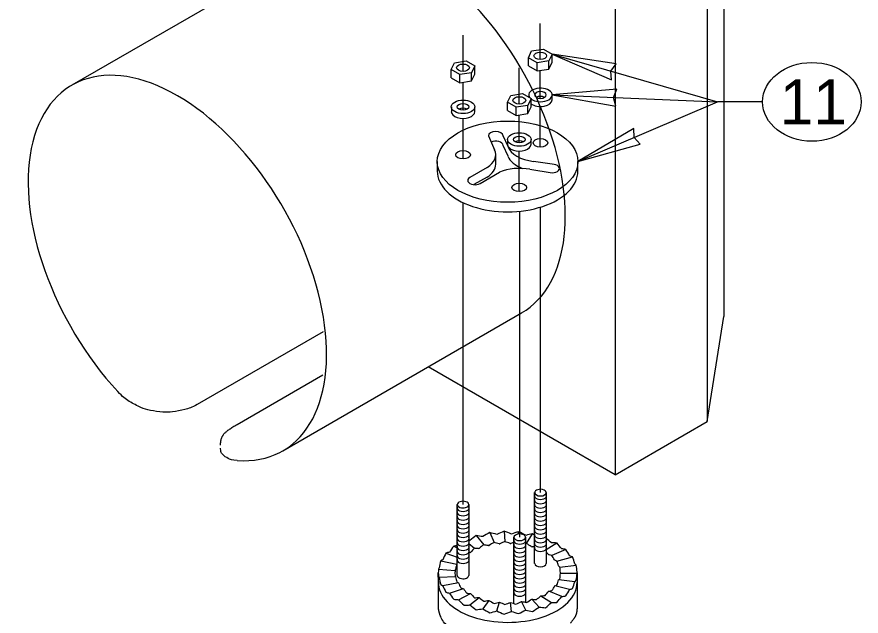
# Model space of a CAD drawing. Extents: x 99862 to 104211, y 98939 to 105076.
# Drawn here: x 100228.4 to 100528.4, y 103913.4 to 104126.3 of the extents above; entities that cross this region are included whole.
import ezdxf

# ---------------------------------------------------------------- set-up
doc = ezdxf.new("R2010")
doc.units = 0
for name, color, linetype in [('Default', 7, 'Continuous'), ('Level 1', 7, 'Continuous'), ('Level 11', 7, 'Continuous'), ('Level 13', 7, 'Continuous'), ('Level 15', 7, 'Continuous'), ('Level 20', 7, 'Continuous'), ('Level 26', 7, 'Continuous')]:
    doc.layers.add(name, color=color, linetype=linetype)

msp = doc.modelspace()

# ---------------------------------------------------------------- linework, layer by layer
at = {"layer": 'Default'}
for p, q in [((100412.41, 103932.12), (100412.41, 103957.28)), ((100412.41, 103932.12), (100412.41, 103957.28)), ((100416.52, 103957.28), (100416.52, 103932.12)), ((100416.52, 103957.28), (100416.52, 103932.12)), ((100384.91, 103927.86), (100384.91, 103953.03)), ((100384.91, 103927.86), (100384.91, 103953.03)), ((100389.02, 103953.03), (100389.02, 103927.86)), ((100389.02, 103953.03), (100389.02, 103927.86)), ((100405.04, 103917.87), (100405.04, 103941.41)), ((100405.04, 103917.87), (100405.04, 103941.41)), ((100409.15, 103941.41), (100409.15, 103918.31)), ((100409.15, 103941.41), (100409.15, 103918.31)), ((100378.18, 103917.02), (100378.18, 103925.41)), ((100427.5, 103925.41), (100427.5, 103917.02))]:
    msp.add_line(p, q, dxfattribs=at)
for centre, start_param, end_param in [((100414.47, 103957.28), 2.356194, 3.141593), ((100414.47, 103957.28), 2.356194, 3.141593), ((100414.47, 103957.28), 3.141593, 6.283185), ((100414.47, 103957.28), 3.141593, 6.283185), ((100414.47, 103957.28), 0, 2.356194), ((100414.47, 103957.28), 0, 2.356194), ((100386.96, 103953.03), 0, 3.141593), ((100386.96, 103953.03), 0, 3.141593), ((100386.96, 103953.03), 3.141593, 4.45059), ((100386.96, 103953.03), 3.141593, 4.45059), ((100386.96, 103953.03), 4.45059, 6.283185), ((100386.96, 103953.03), 4.45059, 6.283185), ((100407.1, 103941.41), 0.261799, 3.141593), ((100407.1, 103941.41), 0.261799, 3.141593), ((100407.1, 103941.41), 3.141593, 6.283185), ((100407.1, 103941.41), 3.141593, 6.283185), ((100407.1, 103941.41), 0, 0.261799), ((100407.1, 103941.41), 0, 0.261799), ((100414.47, 103932.12), 3.141593, 6.283185), ((100414.47, 103932.12), 3.141593, 6.283185), ((100386.96, 103927.86), 3.141593, 4.45059), ((100386.96, 103927.86), 3.141593, 4.45059), ((100386.96, 103927.86), 4.45059, 6.283185), ((100386.96, 103927.86), 4.45059, 6.283185)]:
    msp.add_ellipse(centre, major_axis=(2.05, 0), ratio=0.57735, start_param=start_param, end_param=end_param, dxfattribs=at)
for points, degree in [([(100413.47, 103904.17), (100412.83, 103903.99), (100412.18, 103903.83), (100411.51, 103903.69), (100408.71, 103903.08), (100405.7, 103902.77), (100402.7, 103902.78), (100397.64, 103902.79), (100392.6, 103903.74), (100388.49, 103905.44), (100386.24, 103906.37), (100384.26, 103907.52), (100382.67, 103908.83), (100380.71, 103910.44), (100379.32, 103912.29), (100378.66, 103914.23), (100378.62, 103914.36), (100378.58, 103914.48), (100378.54, 103914.61), (100378.5, 103914.74), (100378.46, 103914.88), (100378.43, 103915.01), (100378.4, 103915.15), (100378.37, 103915.28), (100378.34, 103915.42), (100378.31, 103915.55), (100378.29, 103915.69), (100378.27, 103915.83), (100378.25, 103915.96), (100378.23, 103916.1), (100378.22, 103916.23), (100378.21, 103916.37), (100378.2, 103916.51), (100378.19, 103916.64), (100378.19, 103916.77), (100378.18, 103916.89), (100378.18, 103917.02)], 3), ([(100427.5, 103917.02), (100427.5, 103914.9), (100426.67, 103912.79), (100425.09, 103910.88)], 2)]:
    msp.add_open_spline(points, degree=degree, dxfattribs=at)
at = {"layer": 'Level 1'}
for centre in [(100414.47, 103956.08), (100414.47, 103954.54), (100414.47, 103953), (100386.96, 103951.83), (100386.96, 103950.29), (100414.47, 103951.46), (100414.47, 103949.92), (100386.96, 103948.75), (100386.96, 103947.21), (100414.47, 103948.38), (100414.47, 103946.84), (100386.96, 103945.67), (100386.96, 103944.12), (100414.47, 103945.3), (100414.47, 103943.76), (100386.96, 103942.58), (100386.96, 103941.04), (100414.47, 103942.22), (100414.47, 103940.68), (100386.96, 103939.5), (100386.96, 103937.96), (100407.1, 103940.2), (100407.1, 103938.66), (100414.47, 103939.13), (100414.47, 103937.59), (100386.96, 103936.42), (100386.96, 103934.88), (100407.1, 103937.12), (100407.1, 103935.58), (100386.96, 103933.34), (100407.1, 103934.04), (100407.1, 103932.5), (100407.1, 103930.96), (100407.1, 103929.42), (100407.1, 103927.88), (100407.1, 103926.34), (100407.1, 103924.8), (100407.1, 103923.26), (100407.1, 103921.71)]:
    msp.add_ellipse(centre, major_axis=(-2.13, 0), ratio=0.57735, start_param=6.018236, end_param=9.687845, dxfattribs=at)
at = {"layer": 'Level 11'}
for p, q in [((100411.34, 104114.23), (100415.52, 104114.88)), ((100415.52, 104114.88), (100418.58, 104113.11)), ((100410.22, 104111.82), (100411.34, 104114.23)), ((100410.22, 104108.91), (100410.22, 104111.82)), ((100413.28, 104110.05), (100410.22, 104111.82)), ((100418.58, 104113.11), (100417.46, 104110.7)), ((100418.58, 104110.2), (100418.58, 104113.11)), ((100382.78, 104107.61), (100383.9, 104110.03)), ((100383.9, 104110.03), (100388.08, 104110.67)), ((100388.08, 104110.67), (100391.15, 104108.91)), ((100391.15, 104108.91), (100390.02, 104106.49)), ((100391.15, 104106), (100391.15, 104108.91)), ((100410.22, 104108.91), (100413.28, 104107.14)), ((100417.46, 104110.7), (100413.28, 104110.05)), ((100413.28, 104107.14), (100413.28, 104110.05)), ((100417.46, 104107.79), (100417.46, 104110.7)), ((100417.46, 104107.79), (100418.58, 104110.2)), ((100382.78, 104104.7), (100382.78, 104107.61)), ((100385.84, 104105.84), (100382.78, 104107.61)), ((100390.02, 104106.49), (100385.84, 104105.84)), ((100385.84, 104102.93), (100385.84, 104105.84)), ((100390.02, 104103.58), (100390.02, 104106.49)), ((100390.02, 104103.58), (100391.15, 104106)), ((100413.28, 104107.14), (100417.46, 104107.79)), ((100382.78, 104104.7), (100385.84, 104102.93)), ((100385.84, 104102.93), (100390.02, 104103.58)), ((100402.77, 104096), (100403.89, 104098.42)), ((100403.89, 104098.42), (100408.07, 104099.06)), ((100408.07, 104099.06), (100411.13, 104097.29)), ((100411.13, 104097.29), (100410.01, 104094.88)), ((100410.31, 104098.58), (100410.31, 104097.77)), ((100411.13, 104094.38), (100411.13, 104097.29)), ((100418.64, 104096.88), (100418.64, 104098.58)), ((100382.8, 104094.37), (100382.8, 104092.67)), ((100391.13, 104092.67), (100391.13, 104094.37)), ((100402.77, 104093.09), (100402.77, 104096)), ((100405.83, 104094.23), (100402.77, 104096)), ((100410.01, 104094.88), (100405.83, 104094.23)), ((100405.83, 104091.32), (100405.83, 104094.23)), ((100410.01, 104091.97), (100410.01, 104094.88)), ((100410.01, 104091.97), (100411.13, 104094.38)), ((100402.77, 104093.09), (100405.83, 104091.32)), ((100405.83, 104091.32), (100410.01, 104091.97)), ((100395.96, 104084.04), (100398.18, 104079.08)), ((100402.94, 104080.22), (100401.16, 104084.04)), ((100402.78, 104082.76), (100402.78, 104081.06)), ((100411.12, 104081.06), (100411.12, 104082.76)), ((100402.94, 104076.82), (100401.16, 104080.64)), ((100398.57, 104073.94), (100398.57, 104077.34)), ((100377.81, 104074.89), (100377.81, 104071.49)), ((100395.49, 104072.8), (100389.37, 104069.26)), ((100418.65, 104073.94), (100412.04, 104074.97)), ((100427.8, 104071.49), (100427.8, 104074.89)), ((100393.05, 104067.13), (100399.97, 104071.13)), ((100410.73, 104072.16), (100418.65, 104070.94)), ((100395.49, 104069.4), (100390.84, 104066.71))]:
    msp.add_line(p, q, dxfattribs=at)
for centre, major_axis in [((100414.4, 104112.46), (2.27, 0)), ((100386.96, 104108.26), (2.27, 0)), ((100386.96, 104094.37), (-4.17, 0)), ((100406.95, 104096.65), (2.27, 0)), ((100386.96, 104094.37), (-2.08, 0)), ((100402.8, 104074.89), (-25, 0)), ((100406.95, 104082.76), (-4.17, 0)), ((100406.95, 104082.76), (-2.08, 0)), ((100414.47, 104081.55), (-2.6, 0)), ((100386.96, 104077.34), (-2.6, 0)), ((100406.95, 104065.73), (-2.6, 0))]:
    msp.add_ellipse(centre, major_axis=major_axis, ratio=0.57735, dxfattribs=at)
for centre, major_axis, start_param, end_param in [((100414.47, 104098.58), (-4.17, 0), 0.640708, 6.732556), ((100414.47, 104098.58), (-2.08, 0), 0.014662, 6.296698), ((100414.47, 104096.88), (-4.17, 0), 0.640708, 3.141593), ((100414.47, 104096.88), (-2.08, 0), 3.926991, 5.497787), ((100386.96, 104092.67), (-2.08, 0), 3.926991, 5.497787), ((100386.96, 104092.67), (-4.17, 0), 0, 3.141593), ((100398.56, 104084.04), (-2.6, 0), 3.141593, 6.283185), ((100398.56, 104080.64), (-2.6, 0), 3.141593, 5.379094), ((100406.95, 104081.06), (-2.08, 0), 3.926991, 5.497787), ((100386.96, 104077.34), (-11.61, 0), 2.396309, 3.403392), ((100406.95, 104081.06), (-4.17, 0), 6.283185, 9.424778), ((100414.4, 104081.59), (-11.71, 0), 0.203445, 1.367352), ((100414.4, 104078.19), (-11.71, 0), 0.203445, 1.005854), ((100386.96, 104073.94), (-11.61, 0), 2.396309, 3.141593), ((100407.05, 104065.75), (-11.71, 0), 4.392235, 5.361438), ((100418.65, 104072.44), (-2.6, 0), 1.570796, 4.712389), ((100402.8, 104071.49), (-25, 0), 6.283185, 9.424778), ((100391.21, 104068.2), (-2.6, 0), 5.497787, 8.63938)]:
    msp.add_ellipse(centre, major_axis=major_axis, ratio=0.57735, start_param=start_param, end_param=end_param, dxfattribs=at)
at = {"layer": 'Level 13'}
for p, q in [((100391.64, 103941.99), (100394.33, 103938.71)), ((100396.46, 103943.06), (100397.99, 103939.53)), ((100401.55, 103943.53), (100401.86, 103939.88)), ((100406.7, 103943.37), (100406.49, 103942.54)), ((100409.56, 103939.18), (100411.68, 103942.6)), ((100383.66, 103938.26), (100384.91, 103937.62)), ((100391.05, 103937.48), (100389.02, 103939.06)), ((100395.96, 103938.47), (100396.28, 103938.54)), ((100399.74, 103939.08), (100400.08, 103939.11)), ((100403.65, 103939.21), (100403.99, 103939.2)), ((100411.2, 103938.09), (100411.5, 103938)), ((100420.28, 103939.37), (100416.52, 103936.99)), ((100380.86, 103935.77), (100384.91, 103934.4)), ((100389.46, 103935.98), (100389.71, 103936.12)), ((100392.49, 103937.42), (100392.77, 103937.53)), ((100417.3, 103935.29), (100417.52, 103935.14)), ((100423.53, 103937.06), (100418.56, 103934.97)), ((100379.01, 103932.99), (100384.73, 103931.87)), ((100419.46, 103933.4), (100419.62, 103933.23)), ((100420.34, 103932.95), (100425.87, 103934.41)), ((100378.18, 103925.61), (100378.17, 103928.82)), ((100378.2, 103930.05), (100384.12, 103929.64)), ((100420.9, 103931.3), (100420.99, 103931.11)), ((100421.36, 103930.76), (100427.21, 103931.53)), ((100427.51, 103928.82), (100427.5, 103925.41)), ((100384.33, 103927.38), (100378.47, 103927.08)), ((100426.67, 103925.62), (100420.95, 103926.27)), ((100427.48, 103928.56), (100421.56, 103928.5)), ((100385.34, 103925.19), (100379.81, 103924.2)), ((100382.15, 103921.55), (100387.12, 103923.18)), ((100424.82, 103922.84), (100419.54, 103924.16)), ((100385.4, 103919.23), (100389.58, 103921.42)), ((100389.4, 103917.36), (100392.63, 103919.99)), ((100414.63, 103920.66), (100418.36, 103918.23)), ((100422.02, 103920.34), (100417.41, 103922.26)), ((100396.12, 103918.97), (100394, 103916.01)), ((100398.98, 103915.24), (100399.91, 103918.38)), ((100404.13, 103915.08), (100403.82, 103918.26)), ((100409.23, 103915.55), (100407.69, 103918.62)), ((100414.04, 103916.61), (100411.35, 103919.43))]:
    msp.add_line(p, q, dxfattribs=at)
for centre, major_axis, ratio, start_param, end_param in [((100402.84, 103928.34), (22.78, 14.55), 0.650745, 1.648089, 1.752809), ((100402.84, 103928.34), (-24.35, 10.27), 0.386234, 5.240379, 5.345098), ((100402.84, 103928.34), (23.26, 13.98), 0.588004, 1.492908, 1.597627), ((100402.84, 103928.34), (-24.14, 11.57), 0.440657, 5.077658, 5.182378), ((100402.84, 103928.34), (23.67, 13.17), 0.527399, 1.337713, 1.442432), ((100402.84, 103928.34), (-23.85, 12.69), 0.497899, 4.918981, 5.0237), ((100402.84, 103928.34), (24, 12.15), 0.468967, 1.180574, 1.285294), ((100402.84, 103928.34), (-23.48, 13.6), 0.557438, 4.763018, 4.867737), ((100402.84, 103928.34), (24.25, 10.94), 0.413044, 1.020027, 1.124747), ((100402.84, 103928.34), (-23.03, 14.3), 0.6191, 4.680965, 4.712837), ((100402.84, 103928.34), (-22.52, 14.74), 0.682966, 4.451913, 4.544797), ((100402.84, 103928.34), (21.8, 14.74), 0.783391, 1.97431, 2.078685), ((100402.84, 103928.34), (-24.58, 7.12), 0.292084, 5.610582, 5.687241), ((100402.84, 103928.34), (-24.49, 8.79), 0.335596, 5.40825, 5.427057), ((100402.84, 103928.34), (-17.31, -11.06), 0.650745, 4.789682, 4.885287), ((100402.84, 103928.34), (18.5, -7.8), 0.386234, 2.1079, 2.203506), ((100402.84, 103928.34), (-17.67, -10.62), 0.588004, 4.6345, 4.730106), ((100402.84, 103928.34), (18.34, -8.79), 0.440657, 1.94518, 2.040785), ((100402.84, 103928.34), (-17.99, -10.01), 0.527399, 4.479305, 4.574911), ((100402.84, 103928.34), (18.12, -9.64), 0.497899, 1.786502, 1.882108), ((100402.84, 103928.34), (-18.24, -9.24), 0.468967, 4.361567, 4.417772), ((100402.84, 103928.34), (-18.43, -8.31), 0.413044, 4.16162, 4.184791), ((100402.84, 103928.34), (17.5, -10.86), 0.6191, 1.475639, 1.571245), ((100402.84, 103928.34), (-18.56, -7.26), 0.360362, 4.036609, 4.092053), ((100402.84, 103928.34), (24.54, 7.99), 0.312139, 0.684077, 0.788796), ((100402.84, 103928.34), (-22.02, 14.85), 0.749264, 4.290148, 4.394868), ((100402.84, 103928.34), (21.64, 13.89), 0.853385, 2.16914, 2.27386), ((100402.84, 103928.34), (-24.63, 5.38), 0.252109, 5.762237, 5.866957), ((100402.84, 103928.34), (18.68, -5.41), 0.292084, 2.449758, 2.484365), ((100402.84, 103928.34), (-16.95, -11.19), 0.716006, 4.951048, 5.046939), ((100402.84, 103928.34), (18.61, -6.68), 0.335596, 2.275771, 2.371031), ((100402.84, 103928.34), (16.73, -11.28), 0.749264, 1.15767, 1.220703), ((100402.84, 103928.34), (-18.7, -4.78), 0.270119, 3.648676, 3.744282), ((100402.84, 103928.34), (16.45, -10.98), 0.818147, 0.980127, 1.075733), ((100402.84, 103928.34), (24.61, 6.29), 0.270119, 0.507084, 0.611804), ((100402.84, 103928.34), (-21.65, 14.45), 0.818147, 4.112606, 4.217325), ((100402.84, 103928.34), (24.65, 4.45), 0.236491, 0.323887, 0.428607), ((100402.84, 103928.34), (22.69, 10.5), 0.922162, 2.476441, 2.581161), ((100402.84, 103928.34), (-24.66, 3.49), 0.223561, 5.948263, 6.052982), ((100402.84, 103928.34), (-17.24, -7.98), 0.922162, 5.618034, 5.71364), ((100402.84, 103928.34), (18.74, -2.65), 0.223561, 2.877532, 2.91139), ((100402.84, 103928.34), (-18.73, -3.38), 0.236491, 3.46548, 3.561085), ((100402.84, 103928.34), (16.63, -9.73), 0.888613, 0.750473, 0.846078), ((100402.84, 103928.34), (-21.89, 12.81), 0.888613, 3.882951, 3.987671), ((100402.84, 103928.34), (24.66, 2.51), 0.213589, 0.135385, 0.240105), ((100402.84, 103928.34), (-24.24, 4.82), 0.947565, 0.13373, 0.23845), ((100402.84, 103928.34), (-24.67, 1.51), 0.206802, 6.138761, 6.243481), ((100402.84, 103928.34), (18.42, -3.66), 0.947565, 3.275323, 3.36161), ((100402.84, 103928.34), (18.74, -1.15), 0.206802, 3.006283, 3.101888), ((100402.84, 103928.4), (-18.75, 0), 0.57735, 6.116991, 6.13522), ((100402.84, 103928.34), (-18.74, -1.9), 0.213589, 3.276978, 3.372583), ((100402.84, 103928.34), (18.42, -3.66), 0.947565, 0.23845, 0.34317), ((100402.84, 103928.34), (-18.75, -0.38), 0.203365, 3.085076, 3.189796), ((100402.84, 103928.34), (-24.24, 4.82), 0.947565, 3.380043, 3.484762), ((100402.84, 103928.34), (24.67, 0.5), 0.203365, 6.226668, 6.331388), ((100402.84, 103928.34), (24.67, 0.5), 0.203365, 3.189796, 3.294515), ((100402.84, 103928.34), (-21.89, 12.81), 0.888613, 0.636639, 0.741359), ((100402.84, 103928.34), (-18.75, -0.38), 0.203365, 6.245101, 6.436108), ((100402.84, 103928.34), (16.63, -9.73), 0.888613, 3.778231, 3.882951), ((100402.84, 103928.34), (-16.44, -10.55), 0.853385, 2.27386, 2.378579), ((100402.84, 103928.34), (18.74, -1.15), 0.206802, 6.034041, 6.138761), ((100402.84, 103928.34), (-17.24, -7.98), 0.922162, 2.581161, 2.685881), ((100402.84, 103928.34), (-24.67, 1.51), 0.206802, 2.892449, 2.997168), ((100402.84, 103928.34), (22.69, 10.5), 0.922162, 5.722754, 5.827474), ((100402.84, 103925.41), (24.66, 0), 0.57735, 3.127072, 6.283185), ((100402.84, 103928.34), (24.66, 2.51), 0.213589, 3.381698, 3.486418), ((100402.84, 103928.34), (-21.65, 14.45), 0.818147, 0.866293, 0.971013), ((100402.84, 103928.34), (-18.74, -1.9), 0.213589, 0.240105, 0.344825), ((100402.84, 103928.34), (16.45, -10.98), 0.818147, 4.007886, 4.112606), ((100402.84, 103928.34), (-18.73, -3.38), 0.236491, 0.428607, 0.533326), ((100402.84, 103928.34), (16.73, -11.28), 0.749264, 4.185428, 4.290148), ((100402.84, 103928.34), (-16.57, -11.2), 0.783391, 2.078685, 2.183404), ((100402.84, 103928.34), (18.74, -2.65), 0.223561, 5.843543, 5.948263), ((100402.84, 103928.34), (21.8, 14.74), 0.783391, 5.220277, 5.324997), ((100402.84, 103928.34), (-24.66, 3.49), 0.223561, 2.70195, 2.80667), ((100402.84, 103928.34), (21.64, 13.89), 0.853385, 5.415452, 5.520172), ((100402.84, 103928.34), (24.65, 4.45), 0.236491, 3.570199, 3.674919), ((100402.84, 103928.34), (-22.02, 14.85), 0.749264, 1.043836, 1.148555), ((100402.84, 103928.34), (-18.7, -4.78), 0.270119, 0.611804, 0.716523), ((100402.84, 103928.34), (17.12, -11.2), 0.682966, 4.347193, 4.451913), ((100402.84, 103928.34), (-18.65, -6.07), 0.312139, 0.788796, 0.893516), ((100402.84, 103928.34), (17.5, -10.86), 0.6191, 4.503398, 4.608118), ((100402.84, 103928.34), (-17.31, -11.06), 0.650745, 1.752809, 1.857183), ((100402.84, 103928.34), (18.68, -5.41), 0.292084, 5.477111, 5.582176), ((100402.84, 103928.34), (-16.95, -11.19), 0.716006, 1.914521, 2.019586), ((100402.84, 103928.34), (18.72, -4.09), 0.252109, 5.657863, 5.762237), ((100402.84, 103928.34), (22.3, 14.73), 0.716006, 5.056114, 5.161179), ((100402.84, 103928.34), (-24.63, 5.38), 0.252109, 2.51627, 2.620645), ((100402.84, 103928.34), (24.61, 6.29), 0.270119, 3.753396, 3.858116), ((100402.84, 103928.34), (-22.52, 14.74), 0.682966, 1.2056, 1.31032), ((100402.84, 103928.34), (24.54, 7.99), 0.312139, 3.930389, 4.035109), ((100402.84, 103928.34), (-23.03, 14.3), 0.6191, 1.361805, 1.466525), ((100402.84, 103928.34), (-18.56, -7.26), 0.360362, 0.959575, 1.064294), ((100402.84, 103928.34), (17.84, -10.34), 0.557438, 4.658298, 4.763018), ((100402.84, 103928.34), (-18.43, -8.31), 0.413044, 1.124747, 1.229466), ((100402.84, 103928.34), (18.12, -9.64), 0.497899, 4.814261, 4.918981), ((100402.84, 103928.34), (-18.24, -9.24), 0.468967, 1.285294, 1.390013), ((100402.84, 103928.34), (18.34, -8.79), 0.440657, 4.972938, 5.077658), ((100402.84, 103928.34), (-17.99, -10.01), 0.527399, 1.442432, 1.547152), ((100402.84, 103928.34), (18.5, -7.8), 0.386234, 5.135659, 5.240379), ((100402.84, 103928.34), (-17.67, -10.62), 0.588004, 1.597627, 1.702347), ((100402.84, 103928.34), (18.61, -6.68), 0.335596, 5.30353, 5.40825), ((100402.84, 103928.34), (22.78, 14.55), 0.650745, 4.894402, 4.998776), ((100402.84, 103928.34), (-24.58, 7.12), 0.292084, 2.335518, 2.440583), ((100402.84, 103928.34), (24.43, 9.55), 0.360362, 4.101167, 4.205887), ((100402.84, 103928.34), (-23.48, 13.6), 0.557438, 1.516705, 1.621425), ((100402.84, 103928.34), (24.25, 10.94), 0.413044, 4.266339, 4.371059), ((100402.84, 103928.34), (-23.85, 12.69), 0.497899, 1.672668, 1.777388), ((100402.84, 103928.34), (24, 12.15), 0.468967, 4.426886, 4.531606), ((100402.84, 103928.34), (-24.14, 11.57), 0.440657, 1.831346, 1.936066), ((100402.84, 103928.34), (23.67, 13.17), 0.527399, 4.584025, 4.688745), ((100402.84, 103928.34), (-24.35, 10.27), 0.386234, 1.994066, 2.098786), ((100402.84, 103928.34), (23.26, 13.98), 0.588004, 4.73922, 4.84394), ((100402.84, 103928.34), (-24.49, 8.79), 0.335596, 2.161937, 2.266657)]:
    msp.add_ellipse(centre, major_axis=major_axis, ratio=ratio, start_param=start_param, end_param=end_param, dxfattribs=at)
at = {"layer": 'Level 15'}
for p, q in [((100414.4, 104111.15), (100414.4, 104124)), ((100386.96, 104106.95), (100386.96, 104119.79)), ((100418.58, 104113.11), (100477.45, 104096.11)), ((100406.95, 104095.34), (100406.95, 104108.18)), ((100414.4, 104097.38), (100414.4, 104107.31)), ((100386.96, 104093.17), (100386.96, 104103.11)), ((100418.64, 104098.58), (100477.45, 104096.11)), ((100414.4, 104080.04), (100414.4, 104094.47)), ((100427.8, 104074.89), (100477.45, 104096.11)), ((100493.45, 104096.11), (100477.45, 104096.11)), ((100406.95, 104081.56), (100406.95, 104091.5)), ((100386.96, 104075.84), (100386.96, 104090.27)), ((100406.95, 104064.23), (100406.95, 104078.66)), ((100386.96, 103953.03), (100386.96, 104060.32)), ((100414.47, 103957.28), (100414.47, 104058.72)), ((100407.1, 103941.41), (100407.1, 104057.26))]:
    msp.add_line(p, q, dxfattribs=at)
for points in [[(100418.58, 104113.11), (100439.69, 104103.91), (100439.5, 104107.07), (100441.35, 104109.64)], [(100418.64, 104098.58), (100441.32, 104094.64), (100440.39, 104097.66), (100441.57, 104100.6)], [(100427.8, 104074.89), (100449.97, 104081.12), (100447.83, 104083.45), (100447.62, 104086.61)]]:
    msp.add_lwpolyline(points, close=True, dxfattribs=at)
at = {"layer": 'Level 20'}
msp.add_ellipse((100510.95, 104096.11), major_axis=(-17.5, 0), ratio=0.8, dxfattribs=at)
at = {"layer": 'Level 26'}
for p, q in [((100479.62, 104509.71), (100479.62, 104019.81)), ((100473.75, 104472.42), (100473.75, 103982.52)), ((100440.98, 104453.5), (100440.98, 103963.6)), ((100302.29, 104133.43), (100247.92, 104102.04)), ((100322.92, 103972.13), (100407.77, 104021.12)), ((100473.75, 103982.52), (100479.62, 104019.81)), ((100337.19, 104014.45), (100292.49, 103988.64)), ((100440.98, 103963.6), (100374.56, 104001.95)), ((100306.63, 103981.51), (100337.09, 103999.09)), ((100440.98, 103963.6), (100473.75, 103982.52))]:
    msp.add_line(p, q, dxfattribs=at)
for centre, start_param, end_param in [((100370.27, 104086.08), 0, 2.65862), ((100285.42, 104037.09), 5.909304, 11.369456)]:
    msp.add_ellipse(centre, major_axis=(37.5, -64.95), ratio=0.57735, start_param=start_param, end_param=end_param, dxfattribs=at)
for points, degree in [([(100292.49, 103988.64), (100290.58, 103987.54), (100288.31, 103986.73), (100283.35, 103985.84), (100280.67, 103985.78), (100275.4, 103986.5), (100272.78, 103987.31), (100268.07, 103989.71), (100265.96, 103991.32), (100264.2, 103993.21)], 3), ([(100300.77, 103974.19), (100300.77, 103976.52), (100302.88, 103979.34), (100306.63, 103981.51)], 2), ([(100306.63, 103968.71), (100304.88, 103968.84), (100303.44, 103969.29), (100301.39, 103970.78), (100300.82, 103971.82), (100300.77, 103973.04), (100300.77, 103973.07), (100300.77, 103973.11)], 3)]:
    msp.add_open_spline(points, degree=degree, dxfattribs=at)

# ---------------------------------------------------------------- texts
at = {"layer": 'Level 20'}
msp.add_text('11', height=16, dxfattribs=at).set_placement((100499.57, 104088.11))

doc.saveas('drawing.dxf')
